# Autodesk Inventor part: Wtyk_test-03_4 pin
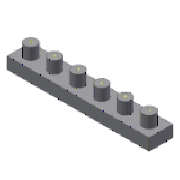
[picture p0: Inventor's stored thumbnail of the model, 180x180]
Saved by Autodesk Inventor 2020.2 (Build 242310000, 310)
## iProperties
Manager: www.cadconsulting.pl
Company: Fabian Stasiak CAD Consulting
Created: 2014-09
Part Number: Wtyk_test-03_4 pin
Material: Ogólny
Document SubType Name: Modeling
Designer: F.Stasiak
Language: pl-PL
Size Designation: 4-Wtyk_test-03_4 pin
Categories: <MemberInstance><Categories><Category DisplayName="Kable i wiązki przewodów" InternalName="e4a7e005-5e42-4d16-b293-125e7f0d0512" Mnemonic="CABLEANDHARNESS"><Cat
Density: 1 g/cm^3
Appearance: Domyślna
Catalog Web Link: www.expertbooks.pl
IsCustomPart: 0
Author: F.Stasiak
Subject: Zbiór ćwiczeń. Autodesk Inventor 2020. Kurs Professional
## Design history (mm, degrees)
sketch "Szkic1"
  geometry: L1 (0, 0)-(60, 0); L2 (0, 5)-(40, 5); L3 (40, 5)-(40, -5); L4 (40, -5)-(0, -5); L5 (0, -5)-(0, 5); 7 further points
  constraints: 10 end point, 2 horizontal, 2 parallel, 1 coincident, 1 midpoint, 1 perpendicular
  dimensions: "d0" = 10 distance of point (15, 0) point (5, 0); "d1" = 10 distance of point (25, 0) point (15, 0) (= d0); "d2" = 10 distance of point (35, 0) point (25, 0) (= d0); "d3" = 10 distance of point (45, 0) point (35, 0) (= d0); "d4" = 10 distance of point (45, 0) point (55, 0) (= d0); "d16" = 5 distance of point (5, 0) L1.start; "d17" = 5 distance of point (55, 0) L1.end (= d16); "d18" = 10 distance of L4.end L2.start; "d19" = 40 distance of L3.end L4.end (= LPINÓW)
node "Oś konstrukcyjna1"
node "Oś konstrukcyjna2"
node "Oś konstrukcyjna3"
node "Oś konstrukcyjna4"
node "Oś konstrukcyjna5"
node "Oś konstrukcyjna6"
extrude "Wyciągnięcie proste3" new body sketch "Szkic1" distance "d20" = 5; taper "d21" = 0 deg
sketch "Szkic3"
  geometry: C1 r 2.5 at (5, 0); 2 further points
  constraints: 1 centre point, 1 coincident
  dimensions: "d22" = 5 diameter of C1
extrude "Wyciągnięcie proste4" join sketch "Szkic3" distance "d23" = 5; taper "d24" = 0 deg
pattern_linear "Szyk prostokątny2" dims "d27" = 10
node "Płaszczyzna konstrukcyjna1"
node "Punkt konstrukcyjny2"
node "Punkt konstrukcyjny3"
node "Punkt konstrukcyjny4"
node "Punkt konstrukcyjny5"
node "Punkt konstrukcyjny6"
node "Punkt konstrukcyjny7"
node "1"
node "2"
node "3"
node "4"
node "5"
node "6"
node "Bryła2"
other parameters: "LPINÓW" = 40 [user parameter; used in 2 equation terms]
